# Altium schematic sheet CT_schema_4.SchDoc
size 282 x 169 mm
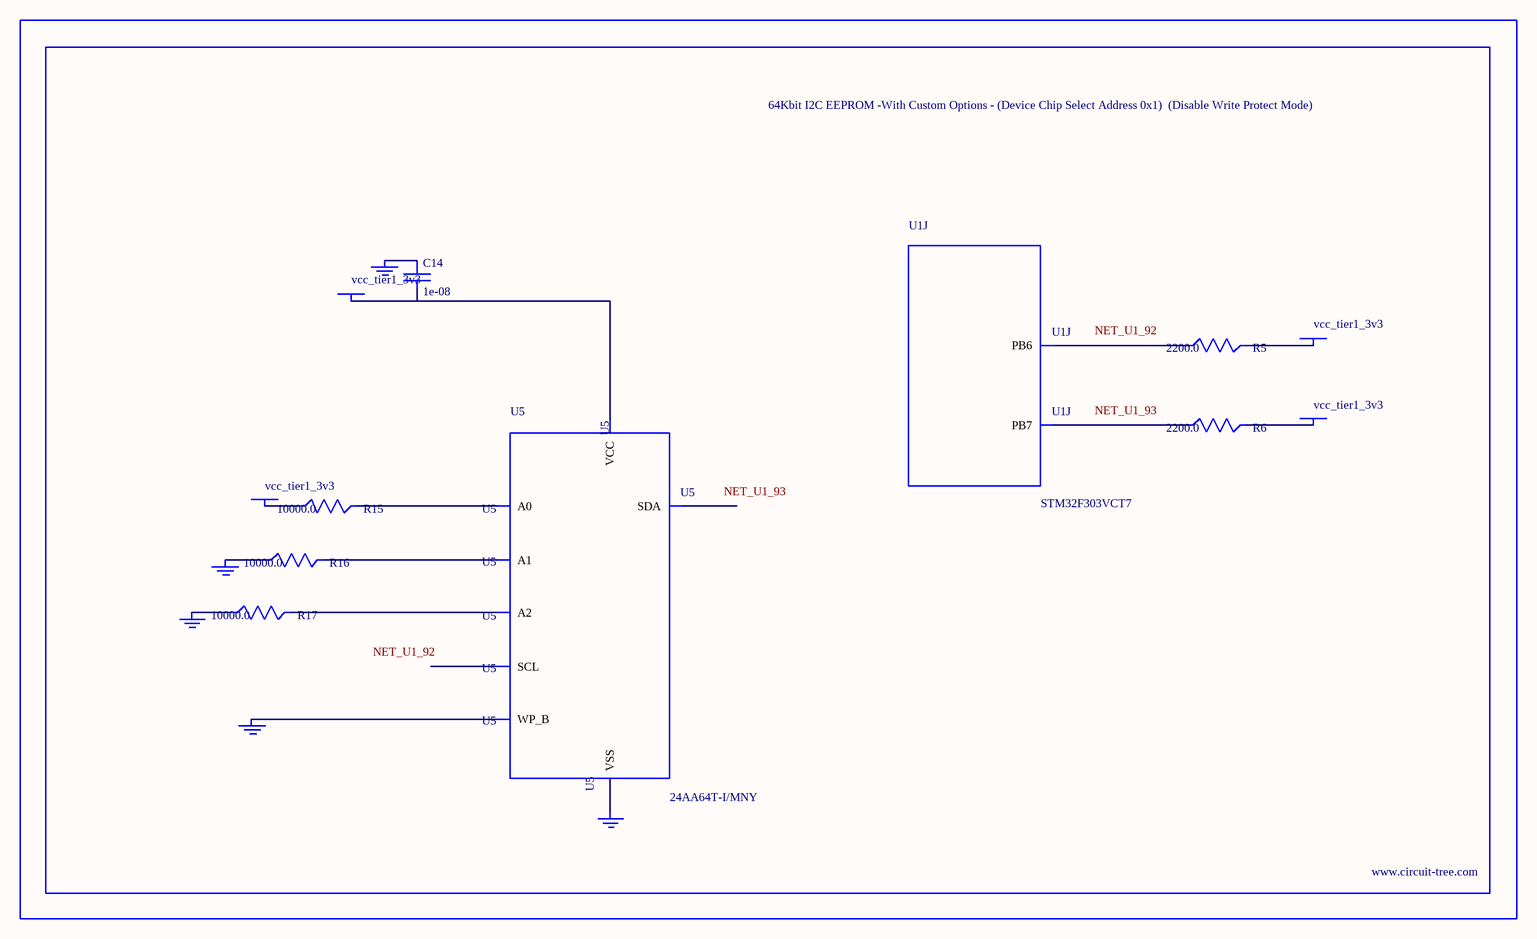
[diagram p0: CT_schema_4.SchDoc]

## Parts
BORDER3  (no value)
C14  1e-08  [C0402]
GND_INSTANCE_3_0  (no value)
GND_INSTANCE_3_1  (no value)
GND_INSTANCE_3_2  (no value)
GND_INSTANCE_3_3  (no value)
GND_INSTANCE_3_4  (no value)
POWER_INSTANCE_3_0  vcc_tier1_3v3
POWER_INSTANCE_3_1  vcc_tier1_3v3
POWER_INSTANCE_3_2  vcc_tier1_3v3
POWER_INSTANCE_3_3  vcc_tier1_3v3
R5  2200.0  [R0603]
R6  2200.0  [R0603]
R15  10000.0  [R0603]
R16  10000.0  [R0603]
R17  10000.0  [R0603]
U1  STM32F303VCT7  [LQFP100]  (part J of 11)
U5  24AA64T-I/MNY  [TDFN-8/6MM]

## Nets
NetC14_1: C14.1 GND_INSTANCE_3_3.0(GND)
NetC14_2: C14.2 POWER_INSTANCE_3_1.0(PWR) U5.8(VCC)
NetGND_INSTANCE_3_0_0: GND_INSTANCE_3_0.0(GND) R16.1
NetGND_INSTANCE_3_1_0: GND_INSTANCE_3_1.0(GND) R17.1
NetGND_INSTANCE_3_2_0: GND_INSTANCE_3_2.0(GND) U5.7(WP_B)
NetGND_INSTANCE_3_4_0: GND_INSTANCE_3_4.0(GND) U5.4(VSS)
NetPOWER_INSTANCE_3_0_0: POWER_INSTANCE_3_0.0(PWR) R15.1
NetPOWER_INSTANCE_3_2_0: POWER_INSTANCE_3_2.0(PWR) R5.2
NetPOWER_INSTANCE_3_3_0: POWER_INSTANCE_3_3.0(PWR) R6.2
NetR5_1: R5.1 U1.92(PB6)
NetR6_1: R6.1 U1.93(PB7)
NetR15_2: R15.2 U5.1(A0)
NetR16_2: R16.2 U5.2(A1)
NetR17_2: R17.2 U5.3(A2)

Not connected (* = marked no-connect by the designer): U5 5(SDA) 6(SCL)

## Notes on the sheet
- Labels drawn without touching a wire or pin: NET_U1_92, NET_U1_93

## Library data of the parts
BORDER3 = BORDER_PAGE3
C14 = C0402C103K3RAC
GND_INSTANCE_3_0-GND_INSTANCE_3_4 = GND
POWER_INSTANCE_3_0-POWER_INSTANCE_3_3 = PWR
R5 R6 = RC0603JR-072K2L
R15-R17 = RC0603JR-0710KL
